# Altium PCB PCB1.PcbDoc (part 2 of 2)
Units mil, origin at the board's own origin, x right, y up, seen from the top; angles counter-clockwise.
Board outline 3937.01 x 3937.01 mil, 2 copper layers (Top Layer, Bottom Layer), stack 65.792 mil thick; 127 components, 100 nets, 530 pads, 138 vias.
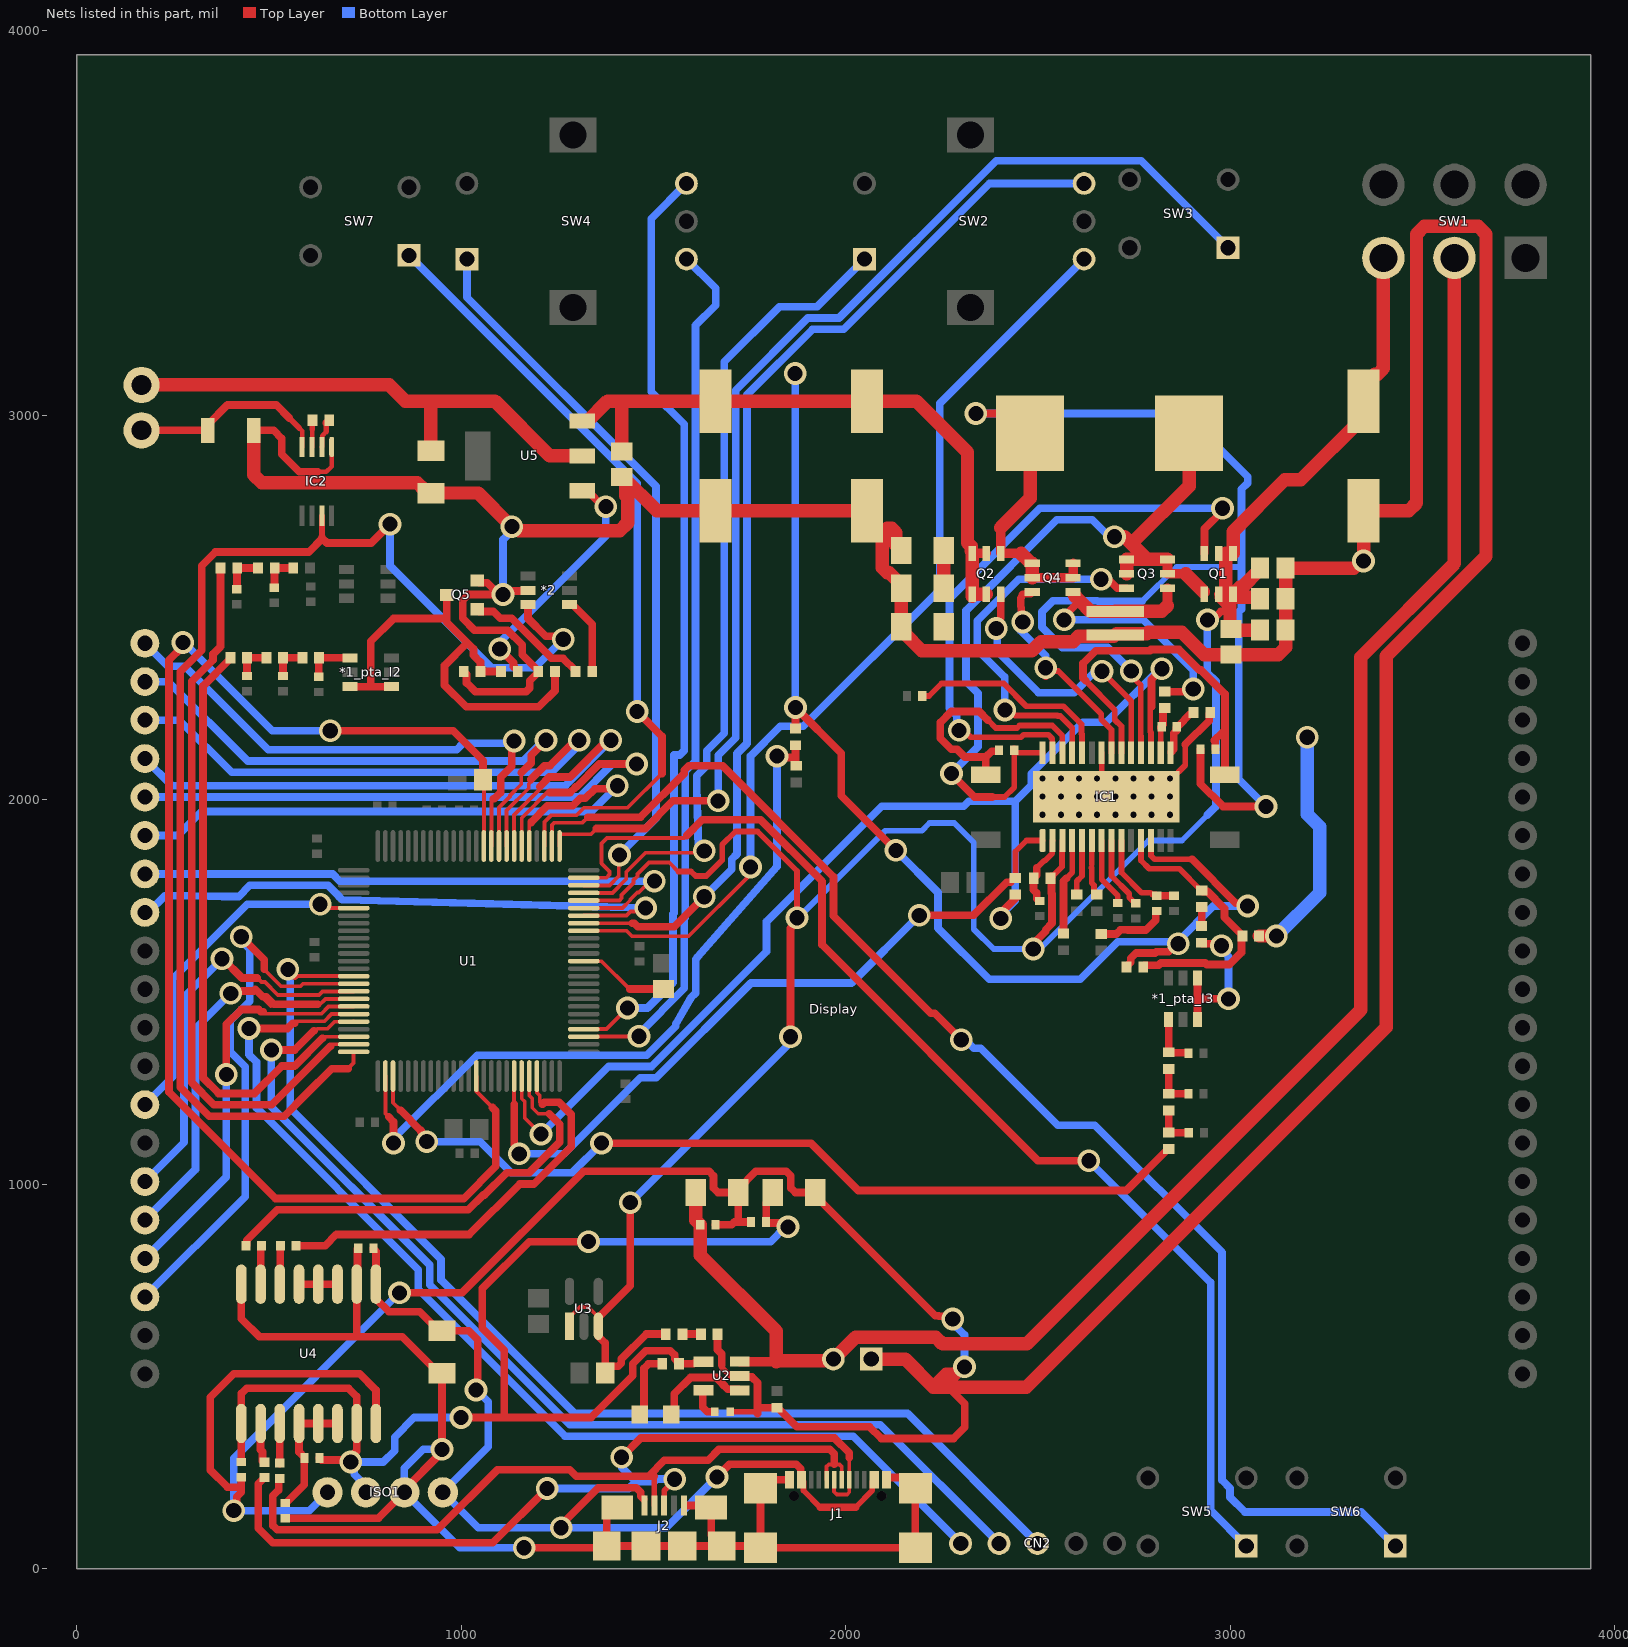
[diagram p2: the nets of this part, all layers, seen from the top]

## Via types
v1: diameter 59.06, hole 39.37, Top Layer to Bottom Layer, 110 vias
v2: diameter 19.68, hole 15.75, Top Layer to Bottom Layer, 12 vias
v3: diameter 19.68, hole 15.75, Top Layer to Bottom Layer, tented top, 6 vias
v4: diameter 19.68, hole 15.75, Top Layer to Bottom Layer, tented both sides, 6 vias
v5: diameter 137.8, hole 118.11, Top Layer to Bottom Layer, 4 vias

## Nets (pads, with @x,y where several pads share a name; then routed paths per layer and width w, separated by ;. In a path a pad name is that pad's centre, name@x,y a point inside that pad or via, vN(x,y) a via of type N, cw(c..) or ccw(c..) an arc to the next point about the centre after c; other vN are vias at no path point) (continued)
Net*1_pta_I2_1: *1_pta_I2.1 C41_pta_I2.2 R22_pta_I2.2 | length 130.8
  Top Layer w20: C41_pta_I2.2@629.11,2319.55 629.6,2320.04 629.6,2368.7 R22_pta_I2.2@630.1,2369.19 630.37,2368.92 710.36,2368.92 *1_pta_I2.1@710.63,2368.64
Net*1_pta_I2_3: *1_pta_I2.3 *1_pta_I2.4 Q5.3 R31.1 R32.2 R33.2 | length 1250.4
  Top Layer w20: *1_pta_I2.3@710.63,2293.84 764.76,2293.84 ; *1_pta_I2.4@818.9,2293.84 764.76,2293.84 ; Q5.3@962.4,2532.48 962.4,2471.06 ; R31.1@1103.35,2333.21 R32.2@1049.76,2333.21 1049.76,2357.75 1031.47,2376.04 1031.47,2392.3 1015.8,2407.97 ; R33.2@1243.55,2333.21 1243.55,2283.46 1201.23,2241.14 1012.81,2241.14 956.38,2297.58 956.38,2348.55 1015.8,2407.97 ; 764.76,2293.84 764.76,2411.99 823.83,2471.06 962.4,2471.06 ; 962.4,2471.06 962.4,2461.37 1015.8,2407.97
Net*1_pta_I3_1: *1_pta_I3.1 C41_pta_I3.2 R22_pta_I3.2 | length 137
  Top Layer w20: *1_pta_I3.1@2839.57,1427.81 R22_pta_I3.2@2839.57,1342.97 2840.78,1341.76 2889.54,1341.76 C41_pta_I3.2@2890.75,1340.55
Net*1_pta_I3_3: *1_pta_I3.3 *1_pta_I3.4 R16.2 | length 390.3
  Top Layer w20: *1_pta_I3.3@2914.37,1427.81 2914.37,1481.95 ; *1_pta_I3.4@2914.37,1536.08 2914.37,1481.95 ; R16.2@2924.86,1627.96 2927.65,1625.16 2971.84,1625.16 v1(2977,1620) ; v1(2995.29,1481.95) 2914.37,1481.95
  Bottom Layer w20: v1(2977,1620) 2977,1609.43 2995.29,1591.14 v1(2995.29,1481.95)
Net*2_3: *2.3 IC2.7 U1.25 | length 3400.7
  Top Layer w10: 705.71,1300.48 720.03,1314.81 U1.25@720.03,1343.96
  Top Layer w15: 637.48,2681.33 IC2.7@637.48,2737.89
  Top Layer w20: 637.48,2681.33 637.07,2680.92 638.91,2679.09 ; 705.71,1300.48 663.02,1300.48 595.74,1233.21 539.51,1176.97 344.25,1176.97 269.2,1252.03 269.2,2332.66 324.99,2388.46 324.99,2608.47 360.3,2643.78 603.6,2643.78 638.91,2679.09 ; v1(814.52,2716.33) 765.52,2667.32 650.67,2667.32 638.91,2679.09 ; *2.3@1173.38,2506.89 1173.38,2471.09 1220,2424.47 1257.53,2424.47 v1(1265,2417)
  Bottom Layer w20: v1(814.52,2716.33) 814.52,2607.84 1079.58,2342.78 1190.78,2342.78 v1(1265,2417)
Net*2_4: *2.4 R34.2 | length 202.7
  Top Layer w20: *2.4@1281.64,2506.89 1289.52,2506.89 1340.45,2455.96 R34.2@1340.45,2333.21
NetC11_2: C11.2 U1.63 | length 237.4
  Top Layer w10: U1.63@1318.46,1580.18 1318.8,1579.83 1364.75,1579.83 1437.23,1507.34 1438.04,1507.34
  Top Layer w20: 1438.04,1507.34 C11.2@1525.69,1507.34
NetC12_2: C12.2 U1.39 U1.86 | length 3570.1
  Top Layer w10: U1.39@1038.93,1280.96 1039.28,1280.62 1039.28,1240.96 1080.89,1199.35 ; U1.86@1058.62,1879.39 C12.2@1058.62,2049.41
  Top Layer w20: v1(275.96,2408.76) 275.96,2398.2 239.7,2361.93 239.7,1239.81 516.95,962.56 1006.09,962.56 1089.93,1046.4 1089.93,1190.31 1080.89,1199.35 ; v1(659.01,2179.01) 978.75,2179.01 1056.54,2101.22 C12.2@1056.54,2051.48 C12.2@1058.62,2049.41
  Bottom Layer w20: v1(275.96,2408.76) 278.69,2408.76 508.45,2179.01 v1(659.01,2179.01)
NetC13_2: C13.2 C14.2 C45.2 C46.2 ISO1.3 R1.2 U2.4 U4.9 U4.15 | length 3318
  Top Layer w20: C45.2@428.03,277.36 U4.9@428.03,377.55 428.03,455.41 441.81,469.19 706.42,469.19 728.03,447.58 U4.15@728.03,377.55 728.03,306.12 712.54,290.64 v1(712.54,277.36) 707.31,282.59 636.41,282.59 C46.2@631.18,287.82 ; v1(999.32,393.33) 1111.77,393.33 ; v1(1330.95,850.45) 1176.74,850.45 1054.86,728.57 1054.86,625.02 1111.77,568.11 1111.77,393.33 ; U2.4@1629.92,538.63 1626.14,534.85 1606.77,534.85 1604.55,532.63 R1.2@1565.95,532.63 1563.15,535.42 1563.15,537.39 1554.93,545.61 1554.93,555.47 1543.51,566.89 1479.59,566.89 1445.83,533.13 1445.83,501.56 1337.6,393.33 1111.77,393.33 ; C13.2@1810.43,978.41 1810.43,969.55 1792.72,951.83 1792.72,899.67 1793.35,899.04 1829.23,899.04 1839.23,889.04 v1(1849.8,889.04)
  Bottom Layer w20: ISO1.3@751.91,198.62 751.91,215.55 721.93,245.53 721.93,267.98 v1(712.54,277.36) 797.25,277.36 826.57,306.68 826.57,342.02 877.88,393.33 v1(999.32,393.33) ; v1(1330.95,850.45) 1804.21,850.45 1842.8,889.04 v1(1849.8,889.04)
NetC15_2: C15.2 C16.2 P1.2 SW1.2 U2.3 | length 4590.2
  Top Layer w25: U2.3@1724.41,538.63 1818.82,538.63
  Top Layer w35: C15.2@1609.64,978.41 1609.64,906.56 C16.2@1621.46,894.75 1621.46,815.37 1818.82,618.01 1818.82,538.63 ; 1818.82,540.61 1962.92,540.61 P1.2@1967.52,545.21 1968.7,545.21 2025.23,601.74 2234.03,601.74 2251.39,584.38 2470.55,584.38 3339.12,1452.96 3339.12,2370.53 3582.68,2614.09 SW1.2@3582.68,3408.86
NetC17_1: C17.1 C23.2 C24.2 C25.2 C26.2 C37.2 IC1.3 Q1.2 R3.2 R6.2 SW1.3 U1.71 U3.1 U3.3 | length 6521.1
  Top Layer w10: U3.1@1281.5,630.49 1281.5,653.98 1292.35,664.83 1292.35,664.98 1307.9,680.53 1329.9,680.53 1356.3,654.13 U3.3@1356.3,652.98 ; U1.71@1318.46,1737.66 1411.12,1737.66 1417.03,1743.56 1417.03,1751.64 1448.15,1782.77 1448.15,1790.85 1457.97,1800.67 1457.97,1806.24 1488.29,1836.55 1540.83,1836.55 1563.98,1813.4
  Top Layer w15: 1563.98,1813.4 1597.43,1813.4 1609.64,1801.18 1637.17,1801.18 1678.3,1842.32 1678.3,1882.71 1712.84,1917.24 1770,1917.24 1872.98,1814.27 v1(1872.98,1692.92) ; R6.2@2536.66,1800.05 2562.05,1825.43 2562.05,1856.91 2562.28,1857.13 2562.28,1866.19 2562.62,1866.53 2562.62,1893.33 IC1.3@2562.99,1893.7
  Top Layer w20: C37.2@1374.22,508.7 C37.2@1374.22,512.64 ; v1(1439.47,951.83) 1439.47,736.15 1356.3,652.98 U3.3@1356.3,630.49 1356.3,604.58 1374.22,586.67 C37.2@1374.22,512.64 ; R3.2@1531.5,610.09 1481.07,610.09 1416.33,545.35 1416.33,534.75 1407.84,526.26 1387.84,526.26 C37.2@1374.22,512.64 ; v1(1856.25,1383.33) 1856.25,1665.62 1872.98,1682.35 v1(1872.98,1692.92) ; v1(2487.45,1611.28) 2487.45,1625.45 2519.6,1657.6 2519.6,1661.96 2536.04,1678.39 2536.04,1755.18 2534.69,1756.52 2534.69,1792.49 R6.2@2531.9,1795.28 2531.9,1797.25 2534.69,1800.05 R6.2@2536.66,1800.05 ; v1(2940.26,2467.38) 2953.53,2467.38 2975.86,2489.71 2986.72,2489.71 2999.01,2477.42
  Top Layer w25: Q1.2@2969.48,2533.95 2988.19,2533.95
  Top Layer w35: Q1.2@2976.67,2526.76 2999.01,2504.42 2999.01,2477.42 2999.01,2455.08 3001.98,2452.11 C23.2@3001.98,2443.96 ; C23.2@3001.98,2440.95 C24.2@3076.77,2440.95 ; Q1.2@3006.89,2526.34 3072.83,2526.34 C25.2@3076.77,2522.4 ; C26.2@3076.77,2602.2 3076.77,2598.27 3030.29,2551.79 3024.73,2551.79 Q1.2@3006.89,2533.95 2988.19,2533.95 2988.19,2640.25 Q1.2@3006.89,2640.25 3006.89,2696.89 3141.56,2831.56 3182.9,2831.56 3346.42,2995.08 C17.1@3346.42,3036.42 3346.42,3077.76 3375.26,3106.6 3382.99,3106.6 3397.64,3121.24 SW1.3@3397.64,3408.86
  Bottom Layer w15: v1@1894.63,1711.14 2102.78,1919.29 2197.71,1919.29 2217.88,1939.46 2281.77,1939.46 2332.84,1888.4 2332.84,1663.09 2384.65,1611.28 2483.84,1611.28 2504.34,1611.28 2786.76,1893.7 2874.02,1893.7 2940.26,1959.94
  Bottom Layer w20: v1(1439.47,951.83) 1856.25,1368.61 v1(1856.25,1383.33) ; 2940.26,1959.94 2962.54,1982.23 2962.54,2308 2940.26,2330.29 v1(2940.26,2467.38)
NetC18_1: C18.1 C19.1 C20.2 C21.2 C22.2 C47.2 IC1.12 Q2.2 R13.2 R29.2 U5.3 | length 4856.5
  Top Layer w15: IC1.12@2793.31,1893.7 2793.68,1893.33 2793.68,1853.94 2802.95,1844.67 2900.41,1844.67
  Top Layer w20: R29.2@1869.05,2184.77 v1(1869.05,2239.54) 1988.15,2120.44 1988.15,2010 v1(2130.03,1868.12) ; R13.2@2730.03,1564.62 2732.83,1567.42 2732.83,1569.39 2741.05,1577.6 2741.05,1587.46 2754.85,1601.27 2803.96,1601.27 2807.46,1604.77 2838.88,1604.77 2859.11,1625 v1(2864.4,1625) ; 2900.41,1844.67 3014.32,1730.76 3037.43,1730.76 v1(3044.9,1723.29)
  Top Layer w25: Q2.2@2328.21,2640.25 Q2.2@2365.61,2640.25
  Top Layer w35: U5.3@1314.42,2984.25 1328.2,2984.25 1380.36,3036.42 1421.26,3036.42 ; C47.2@1417.32,2905.51 1417.32,3032.48 1421.26,3036.42 ; C21.2@2254.34,2549.7 C22.2@2254.34,2647.64 ; Q2.2@2325.55,2647.43 2325.55,2658.51 2316.35,2667.72 2316.35,2903.6 2183.52,3036.42 C19.1@2055.08,3036.42 C18.1@1661.38,3036.42 1421.26,3036.42 ; Q2.2@2328.21,2529.42 Q2.2@2328.21,2533.95 ; Q2.2@2328.21,2640.25 Q2.2@2328.21,2533.95 ; Q2.2@2365.61,2533.95 Q2.2@2328.21,2533.95
  Bottom Layer w20: v1(1868.07,3108.27) 1868.56,3107.78 1868.56,2240.03 v1(1869.05,2239.54) ; v1(2130.03,1868.12) 2239.76,1758.39 2239.76,1665.9 2372.92,1532.75 2609.53,1532.75 2707.55,1630.77 2862.88,1630.77 2955.4,1723.29 v1(3044.9,1723.29)
NetC27_1: C27.1 IC1.2 R6.1 | length 188.3
  Top Layer w15: 2496.38,1821.97 2515.29,1840.87 2518.12,1840.87 2537.03,1859.78 2537.03,1893.33 IC1.2@2537.4,1893.7
  Top Layer w20: R6.1@2488.59,1795.28 R6.1@2487.85,1794.54 ; 2496.38,1821.97 2496.38,1803.08 R6.1@2487.85,1794.54 ; C27.1@2503.94,1736.47 2501.97,1736.47 2496.34,1742.1 2496.34,1757.03 2487.85,1765.52 R6.1@2487.85,1794.54
NetC28_1: C28.1 IC1.28 L1.1 Q1.1 Q3.2 | length 2084
  Top Layer w15: 2380.7,2006.66 2412.58,2006.66 2437.79,2031.87 C28.1@2437.79,2126.7 ; C28.1@2437.79,2128.67 C28.1@2437.79,2126.7 ; IC1.28@2511.81,2122.05 2442.44,2122.05 C28.1@2437.79,2126.7
  Top Layer w20: v1(2274.56,2068.01) 2274.56,2066.88 2334.78,2006.66 2380.7,2006.66 ; C28.1@2437.16,2131.26 2437.16,2129.3 C28.1@2437.79,2128.67
  Top Layer w25: Q3.2@2836.5,2624.5 Q3.2@2836.5,2587.1 2883.46,2587.1
  Top Layer w35: v1(2698.86,2683.75) 2724.64,2683.2 2742.68,2665.17 2783.35,2624.5 ; Q3.2@2730.2,2587.1 Q3.2@2730.2,2624.5 2783.35,2624.5 ; 2750.31,2672.8 2892.47,2814.96 L1.1@2892.47,2952.76 ; Q3.2@2836.5,2624.5 2783.35,2624.5 ; 2883.46,2587.1 Q1.1@2929.42,2541.13
  Bottom Layer w20: v1(2274.56,2068.01) 2343.77,2137.23 2343.77,2276.23 2312.47,2307.53 2312.47,2491.61 2548.99,2728.13 2640.74,2728.13 2685.11,2683.75 v1(2698.86,2683.75)
NetC28_2: C28.2 D2.1 IC1.26 | length 673.2
  Top Layer w15: 2369.37,2206.83 2389.73,2186.47 2445.29,2186.47 2451.89,2193.08 2536.88,2193.08 2562.99,2166.96 IC1.26@2562.99,2122.05
  Top Layer w20: D2.1@2364.09,2064.97 2364.09,2110.87 ; 2369.37,2206.83 2347.16,2229.05 2274.44,2229.05 2245.72,2200.33 2245.72,2159.71 2274.44,2130.99 2288.99,2130.99 2309.11,2110.87 2364.09,2110.87 ; C28.2@2398.42,2128.67 2398.42,2126.7 2397.79,2126.07 2379.29,2126.07 2364.09,2110.87
NetC29_1: C29.1 IC1.16 R9.1 | length 122.2
  Top Layer w15: IC1.16@2818.9,2122.05 C29.1@2818.9,2187.37
  Top Layer w20: C29.1@2818.9,2187.37 C29.1@2821.39,2189.86 ; C29.1@2822.02,2188.63 2822.02,2192.46 2824.8,2195.24 2824.8,2235.24 2827.59,2238.03 R9.1@2829.26,2238.03
NetC29_2: C29.2 IC1.15 R12.1 | length 137.4
  Top Layer w15: IC1.15@2844.49,2122.05 IC1.15@2847.02,2124.58
  Top Layer w20: IC1.15@2847.02,2124.58 2853.03,2130.59 2853.03,2172.35 2860.13,2179.44 2860.13,2187.26 2860.76,2187.89 C29.2@2860.76,2189.86 ; C29.2@2861.03,2187.79 2861.03,2192.11 2861.39,2192.46 2865.71,2192.46 2894.87,2221.62 2901.39,2221.62 2904.19,2224.42 R12.1@2904.19,2226.38
NetC30_2: C30.2 IC1.8 | length 190.5
  Top Layer w15: IC1.8@2690.95,1893.7 2690.95,1801.27 2736.82,1755.4 2736.82,1745.19 2751.69,1730.32 C30.2@2753.66,1730.32
NetC32_1: C32.1 IC1.18 L1.2 Q2.1 Q4.2 | length 3847.7
  Top Layer w15: v1(2742.13,2334.57) 2742.13,2322.65 2766.63,2298.15 2766.63,2166.81 2767.72,2165.72 IC1.18@2767.72,2122.05
  Top Layer w20: v1(2338.05,3003.94) 2427.9,3003.94 L1.2@2479.09,2952.76 ; C32.1@2922.1,2131.26 2922.1,2041.13 2981,1982.23 v1(3092.52,1982.23)
  Top Layer w25: 2403.01,2707.55 Q2.1@2403.01,2640.25 2455.67,2640.25 ; Q4.2@2484.83,2577.25 Q4.2@2591.13,2577.25 Q4.2@2591.13,2614.65
  Top Layer w35: 2403.01,2707.55 2479.09,2783.63 L1.2@2479.09,2952.76 ; 2455.67,2640.25 2477.64,2618.27 2477.64,2617.31 2480.3,2614.65 Q4.2@2484.83,2614.65 Q4.2@2484.83,2577.25
  Bottom Layer w15: 2771.07,2515.81 2860.07,2604.81 3028.7,2604.81
  Bottom Layer w20: v1(2338.05,3003.94) 2880.77,3003.94 3044.87,2839.85 3044.87,2823.28 3028.7,2807.11 3028.7,2604.81 3028.7,2494.85 3021.66,2487.81 3021.66,2053.09 v1(3092.52,1982.23) ; v1(2742.13,2334.57) 2681.15,2395.54 2562.68,2395.54 2510.03,2448.2 2510.03,2488.81 2538.75,2517.53 2654.05,2517.53 2655.77,2515.81 2771.07,2515.81
NetC32_2: C32.2 D3.1 IC1.20 | length 969.4
  Top Layer w15: 2623.82,2308.86 2699.31,2233.38 2699.31,2207.79 2716.54,2190.56 IC1.20@2716.54,2122.05
  Top Layer w20: 2623.82,2308.86 2616.93,2315.75 2616.93,2354.23 2650.19,2387.49 2790.82,2387.49 2793.51,2390.18 2866.34,2390.18 2919.66,2336.86 2923.59,2336.86 2985.88,2274.57 D3.1@2985.88,2064.97 ; C32.2@2961.47,2131.26 2960.84,2131.89 2960.84,2151.13 2958.11,2153.86 2979.79,2175.54
NetC33_1: C33.1 R18.2 | length 183.7
  Top Layer w20: R18.2@2664.01,1650.6 2703.6,1650.6 2714.45,1661.45 2732.35,1661.45 2732.98,1660.82 2780.07,1660.82 2805.86,1686.6 2805.86,1707.72 2806.17,1708.04 2806.17,1710 2806.8,1710.63 C33.1@2808.77,1710.63
NetC33_2: C33.2 C35.2 IC1.9 | length 245.3
  Top Layer w15: IC1.9@2716.54,1893.7 2716.54,1810.33 2768.92,1757.95 2792.48,1757.95 2797.29,1753.13 2805.64,1753.13 C33.2@2808.77,1750
  Top Layer w20: C33.2@2808.77,1750 C35.2@2853.52,1750.01
NetC34_2: C34.2 IC1.7 | length 179.7
  Top Layer w15: IC1.7@2665.35,1893.7 2665.35,1792.22 2707.22,1750.35 C34.2@2707.22,1731.3
NetC39_pta_I1_2: C39_pta_I1.2 R20_pta_I1.2 R21_pta_I1.1 | length 109.7
  Top Layer w20: C39_pta_I1.2@416.34,2547.24 416.83,2547.74 416.83,2601.87 R20_pta_I1.2@417.32,2602.36 R21_pta_I1.1@471.46,2602.36
NetC39_pta_I2_2: C39_pta_I2.2 R20_pta_I2.2 R21_pta_I2.1 | length 97.7
  Top Layer w20: C39_pta_I2.2@442.87,2321.4 R20_pta_I2.2@442.87,2368.64 443.14,2368.92 492.84,2368.92 R21_pta_I2.1@493.11,2369.19
NetC39_pta_I3_2: C39_pta_I3.2 R20_pta_I3.2 R21_pta_I3.1 | length 109.7
  Top Layer w20: R20_pta_I3.2@2839.57,1134.51 R21_pta_I3.1@2839.57,1191.59 ; R20_pta_I3.2@2839.57,1134.51 2840.06,1134.01 2891.3,1134.01 C39_pta_I3.2@2891.79,1133.52
NetC40_pta_I1_2: C40_pta_I1.2 R21_pta_I1.2 R22_pta_I1.1 | length 100
  Top Layer w20: C40_pta_I1.2@513.78,2551.18 514.28,2551.67 514.28,2601.87 R21_pta_I1.2@514.77,2602.36 R22_pta_I1.1@563.16,2602.36
NetC40_pta_I2_2: C40_pta_I2.2 R21_pta_I2.2 R22_pta_I2.1 | length 98.2
  Top Layer w20: C40_pta_I2.2@536.42,2321.4 R21_pta_I2.2@536.42,2369.19 R22_pta_I2.1@586.79,2369.19
NetC40_pta_I3_2: C40_pta_I3.2 R21_pta_I3.2 R22_pta_I3.1 | length 115.9
  Top Layer w20: R22_pta_I3.1@2839.57,1299.66 R21_pta_I3.2@2839.57,1234.9 C40_pta_I3.2@2890.75,1234.9
NetC42_1: C42.1 C43.1 C44.2 ISO1.2 J1.1 J1.2 J1.3 J1.4 J1.A1-B12 J1.B1-A12 J2.5 J2.6 J2.7 J2.8 J2.9 J2.10 J2.11 U4.2 U4.8 | length 3933.5
  Top Layer w20: U4.8@428.03,739.75 428.03,650.1 475.17,602.95 728.03,602.95 ; C44.2@541.81,131.21 784.5,131.21 ISO1.2@851.91,198.62 ; C43.1@732.11,833.21 730.07,831.17 730.07,741.79 U4.2@728.03,739.75 728.03,602.95 ; ISO1.2@848.49,202.04 949.88,303.43 v1(949.88,310.26) C42.1@949.88,508.7 941.02,508.7 846.77,602.95 728.03,602.95 ; v1(1163.39,54.28) 1373.18,54.28 J2.8@1377.95,59.06 ; J2.6@1404.45,159.45 1377.95,132.95 J2.8@1377.95,59.06 ; 1586.61,164.37 1644.69,164.37 J2.7@1649.61,159.45 1649.61,86.61 J2.9@1677.17,59.06 ; J1.A1-B12@1853.35,231.65 1800.79,231.65 J1.1@1778.15,209.01 J1.3@1778.15,54.28 ; J1.B1-A12@2105.31,231.65 2111.02,237.36 2152.16,237.36 J1.2@2180.51,209.01 J1.4@2180.51,54.28 J1.3@1778.15,54.28 ; J2.8@1377.95,59.06 J2.11@1574.8,59.06 J2.9@1677.17,59.06 ; J2.9@1677.17,59.06 1773.38,59.06 J1.3@1778.15,54.28
  Bottom Layer w20: v1(949.88,310.26) 900.81,310.26 851.91,261.36 ISO1.2@851.91,198.62 996.25,54.28 v1(1163.39,54.28)
NetC42_2: C42.2 C43.2 ISO1.1 J1.A4-B9 J1.B4-A9 J2.1 U4.1 | length 2522.9
  Top Layer w15: J1.A4-B9@1884.84,231.65 1890.03,226.46 1890.03,203 1933.58,159.45 ; 2025.08,159.45 2068.63,203 2068.63,226.46 J1.B4-A9@2073.82,231.65
  Top Layer w20: C43.2@771.48,833.21 771.48,831.24 778.03,824.69 778.03,702.35 812.17,668.21 891.75,668.21 C42.2@941.02,618.93 ; C42.2@949.88,618.93 1019.23,618.93 1042.87,595.29 1042.87,469.19 v1(1038.46,464.78) ; v1(1259.64,106.45) 1259.64,113.99 1356.1,210.45 1454.93,210.45 1466.35,199.02 1466.35,188.85 J2.1@1474.25,180.95 ; v1(1664.75,238.46) 1697.55,271.26 1871.31,271.26 1883.03,259.54 1883.03,233.46 J1.A4-B9@1884.84,231.65 ; 1933.58,159.45 2025.08,159.45
  Bottom Layer w20: v1(1038.46,464.78) 1039.42,464.78 1070.43,433.78 1070.43,317.14 ISO1.1@951.91,198.62 1044.08,106.45 v1(1259.64,106.45) 1532.74,106.45 v1(1664.75,238.46)
NetC44_1: C44.1 C46.1 U4.12 U4.13 U4.14 | length 334.5
  Top Layer w20: C44.1@541.81,170.58 543.78,170.58 591.81,218.61 591.81,289.79 578.03,303.57 U4.12@578.03,377.55 U4.13@628.03,377.55 U4.14@678.03,377.55
NetC48_2: C48.2 CN1.1 U5.2 | length 1351.3
  Top Layer w35: CN1.1@168.5,3078.29 812.55,3078.29 854.42,3036.42 920.94,3036.42 ; C48.2@920.94,2907.48 920.94,3036.42 ; U5.2@1314.42,2893.7 1230.32,2893.7 1087.6,3036.42 920.94,3036.42
NetCN1_2: CN1.2 IC2.4 R27.1 | length 523.6
  Top Layer w12: 578.57,2966.33 586.3,2958.6 IC2.4@586.3,2917.03
  Top Layer w15: 552.39,2992.52 578.57,2966.33
  Top Layer w20: CN1.2@168.5,2960.18 R27.1@340.42,2960.18 340.42,2974.94 391.9,3026.43 518.47,3026.43 552.39,2992.52
NetCN2_1: CN2.1 U1.20 | length 2837.4
  Top Layer w10: 561.72,1418.69 566.72,1423.69 644.14,1423.69 662.83,1442.38 U1.20@720.03,1442.38
  Top Layer w20: v1(448,1405) 548.03,1405 561.72,1418.69 566.72,1418.69
  Bottom Layer w20: v1(448,1405) 448,1337.05 467.53,1317.53 467.53,1198.23 888.14,777.61 888.14,726.45 1269.9,344.69 2019.28,344.69 CN2.1@2298.43,65.55
NetCN2_2: CN2.2 U1.21 | length 2783.9
  Top Layer w10: 618.53,1397.41 625.32,1404.19 652.22,1404.19 670.38,1422.35 719.69,1422.35 U1.21@720.03,1422.7
  Top Layer w20: v1(506,1349) 566.55,1349 616.74,1399.19
  Bottom Layer w20: v1(506,1349) 506,1201.47 917.64,789.83 917.64,738.67 1282.12,374.19 2089.78,374.19 CN2.2@2398.43,65.55
NetCN2_3: CN2.3 U1.15 | length 2986.1
  Top Layer w10: v1@566.55,1540.99 719.85,1540.99 U1.15@720.03,1540.81
  Top Layer w20: v1(549.02,1558.52) v1@566.55,1540.99
  Bottom Layer w20: v1(549.02,1558.52) 555.03,1552.52 555.03,1196.95 947.14,804.84 947.14,750.89 1294.34,403.69 2160.28,403.69 CN2.3@2498.43,65.55
NetDisplay_23: Display.23 U1.16 | length 1454.5
  Top Layer w10: 487.77,1558.52 487.77,1557.51 530.78,1514.5 581.54,1514.5 588.16,1521.12 U1.16@720.03,1521.12
  Top Layer w20: v1(427.69,1643.41) 487.77,1583.33 487.77,1558.52
  Bottom Layer w20: Display.23@177.17,706.69 438.03,967.56 438.03,1305.31 398.97,1344.36 398.97,1425.31 427.69,1454.03 449.47,1475.8 449.47,1611.06 427.69,1632.84 v1(427.69,1643.41)
NetDisplay_24: Display.24 U1.19 | length 1060.8
  Top Layer w10: 479.06,1448.19 484.06,1443.19 636.07,1443.19 654.94,1462.07 U1.19@720.03,1462.07
  Top Layer w20: v1(389,1285) 389,1415.34 427.69,1454.03 473.23,1454.03 479.06,1448.19 484.06,1448.19
  Bottom Layer w20: Display.24@177.17,806.69 389,1018.53 v1(389,1285)
NetDisplay_25: Display.25 U1.18 | length 1064.6
  Top Layer w10: 480.1,1487.19 486.51,1480.79 504.6,1462.69 ; 625.92,1462.69 627.99,1462.69 647.05,1481.75 U1.18@720.03,1481.75
  Top Layer w20: v1(400.44,1496.11) 406.81,1502.48 459.97,1502.48 464.18,1506.69 483.68,1487.19 492.91,1487.19 512.41,1467.69 625.92,1467.69
  Bottom Layer w20: Display.25@177.17,906.69 308.56,1038.09 308.56,1404.23 v1(400.44,1496.11)
NetDisplay_26: Display.26 U1.17 | length 1047.2
  Top Layer w10: 468.86,1536.67 480.23,1525.3 489.46,1525.3 522.56,1492.19 629.91,1492.19 639.15,1501.44 U1.17@720.03,1501.44
  Top Layer w20: v1(377.91,1586.08) 379.81,1586.08 429.69,1536.19 468.49,1536.19
  Bottom Layer w20: Display.26@177.17,1006.69 279.06,1108.59 279.06,1487.24 v1(377.91,1586.08)
NetDisplay_28: Display.28 U1.6 | length 912.6
  Top Layer w10: v1(633,1728) 646.27,1728 656.3,1717.97 U1.6@720.03,1717.97
  Bottom Layer w20: Display.28@177.17,1206.69 249.56,1279.09 249.56,1534.61 442.95,1728 v1(633,1728)
NetDisplay_33: Display.33 U1.69 | length 1517.8
  Top Layer w10: U1.69@1318.46,1698.29 1429.71,1698.29 1440.19,1708.76 1470.05,1708.76 v1(1479.44,1718.15)
  Bottom Layer w20: Display.33@177.17,1706.69 186.19,1706.69 229.41,1749.91 301.88,1749.91 379.15,1747.83 421.06,1747.83 450.26,1777.03 653.31,1777.03 682.03,1748.31 682.03,1747.71 690.25,1739.49 1479.44,1718.31 v1(1479.44,1718.15)
NetDisplay_34: Display.34 U1.70 | length 1546.3
  Top Layer w10: U1.70@1318.46,1717.97 1419.02,1717.97 1439.19,1738.14 1439.19,1740.16 1448.3,1749.28 1457.42,1758.4 1461.59,1758.4 v1@1491.2,1788
  Top Layer w20: v1@1491.2,1788 v1(1502,1788)
  Bottom Layer w20: Display.34@177.17,1806.69 177.33,1806.53 665.53,1806.53 684.05,1788 v1(1502,1788)
NetDisplay_35: Display.35 U1.80 | length 1611.5
  Top Layer w10: U1.80@1176.73,1879.39 1176.72,1940.41 1179.13,1942.82
  Top Layer w20: 1181.54,1940.41 1181.54,1941.61 1223.97,1984.04 1290.19,1984.04 1309.33,2003.18 1322.42,2003.18 1347.86,2028.62 1398.43,2028.62 v1(1405.9,2036.1)
  Bottom Layer w20: Display.35@177.17,1906.69 262.64,1906.69 325.16,1969.22 1339.02,1969.22 v1(1405.9,2036.1)
NetDisplay_36: Display.36 U1.81 | length 1742.3
  Top Layer w10: U1.81@1157.04,1879.39 1157.04,1952.55 1226.76,2022.27
  Top Layer w20: 1230.3,2018.74 1283.16,2018.74 1297.11,2032.68 1298.49,2032.68 1358.34,2092.53 v1(1455.96,2092.53)
  Bottom Layer w20: Display.36@177.17,2006.69 1307.16,2006.69 1393,2092.53 v1(1455.96,2092.53)
NetDisplay_37: Display.37 U1.82 | length 1710.1
  Top Layer w10: U1.82@1137.36,1879.39 1137.36,1960.44 1210.95,2034.04
  Top Layer w20: 1203.65,2033.81 1228.55,2058.71 1282.8,2058.71 1378.35,2154.26 v1(1388.92,2154.26)
  Bottom Layer w20: Display.37@177.17,2106.69 247.67,2036.19 1270.85,2036.19 v1(1388.92,2154.26)
NetDisplay_38: Display.38 U1.83 | length 1592.5
  Top Layer w10: U1.83@1117.67,1879.39 1117.67,1971.63 1175.45,2029.4 1175.45,2040.26 1183.99,2048.79
  Top Layer w20: 1180.45,2052.33 1216.33,2088.21 1230.47,2088.21 1296.77,2154.51 v1(1306.38,2154.51)
  Bottom Layer w20: Display.38@177.17,2206.69 266.93,2206.69 402.64,2070.98 1234.61,2070.98 1306.99,2143.36 1306.99,2153.9 v1(1306.38,2154.51)
NetDisplay_39: Display.39 U1.84 | length 1476.3
  Top Layer w10: U1.84@1097.99,1879.39 1097.99,1979.52 1126.97,2008.5 1126.97,2011.07 1155.95,2040.05 1155.95,2069.55
  Top Layer w20: 1155.95,2069.55 1181.54,2095.14 1181.54,2115.53 v1(1220.27,2154.26)
  Bottom Layer w20: Display.39@177.17,2306.69 238.06,2306.69 444.27,2100.48 1161.22,2100.48 1214.99,2154.26 v1(1220.27,2154.26)
NetDisplay_40: Display.40 U1.85 | length 1414.8
  Top Layer w10: U1.85@1078.3,1879.39 1078.3,2001.55 1102.47,2025.72
  Top Layer w20: 1083.12,2001.86 1085.68,2001.86 1102.47,2018.65 1102.47,2025.72 1102.47,2057.78 1131.45,2086.77 1131.45,2146.38 v1(1137.36,2152.29)
  Bottom Layer w20: Display.40@177.17,2406.69 236.98,2346.87 281.17,2346.87 498.06,2129.98 988.01,2129.98 1004.41,2146.38 1131.45,2146.38 v1(1137.36,2152.29)
NetIC1_1: IC1.1 R7.2 U1.44 | length 1949.6
  Top Layer w10: 1137.36,1207.36 U1.44@1137.36,1283.92
  Top Layer w15: R7.2@2440.95,1796.27 2440.95,1865.01 2469.64,1893.7 IC1.1@2511.81,1893.7
  Top Layer w20: 1137.36,1207.36 1137.36,1102.65 1150.65,1089.36 v1(1150.65,1078.79) ; v1(2190.74,1699.07) 2331.92,1699.07 2418.11,1785.25 2427.96,1785.25 2436.18,1793.47 2438.15,1793.47 R7.2@2440.95,1796.27
  Bottom Layer w20: v1(1150.65,1078.79) 1267.58,1078.79 1465.39,1276.6 1506.98,1276.6 1753.48,1523.09 2014.76,1523.09 v1(2190.74,1699.07)
NetIC1_4: IC1.4 R8.2 | length 251.6
  Top Layer w15: 2573.72,1795.28 2588.58,1810.14 IC1.4@2588.58,1893.7
  Top Layer w20: R8.2@2565.93,1651.44 2565.93,1787.49 2573.72,1795.28
NetIC1_5: IC1.5 R14.2 | length 146.4
  Top Layer w15: R14.2@2600.83,1753 2600.83,1758.14 2600.72,1758.25 2600.72,1787.63 2614.17,1801.09 IC1.5@2614.17,1893.7
  Top Layer w20: R14.2@2600.8,1752.96 R14.2@2600.87,1753.03
NetIC1_6: IC1.6 R10.2 | length 139
  Top Layer w15: 2638.67,1822.64 2639.76,1821.55 2639.76,1783.16 2645.7,1777.22 2645.7,1758.3 2650.99,1753.01 R10.2@2652.96,1753.01 ; 2639.76,1831.45 IC1.6@2639.76,1893.7
NetIC1_11: IC1.11 R13.1 R15.1 R17.2 | length 730.2
  Top Layer w15: IC1.11@2767.72,1893.7 2767.72,1841.7 2767.87,1841.55 2789.25,1820.17 2867.48,1820.17 2923.87,1763.78 R15.1@2925.84,1763.78
  Top Layer w20: R13.1@2773.34,1564.62 2773.34,1566.59 2776.14,1569.39 2813.8,1569.39 2819.68,1575.27 2934.26,1575.27 2938.55,1570.97 2997.31,1570.97 3028.7,1602.36 3028.7,1642.56 R17.2@3031.5,1645.35 ; R15.1@2925.84,1763.78 2928.64,1760.99 2940.47,1760.99 2984.58,1716.87 2984.58,1694.23 3028.7,1650.12 R17.2@3028.7,1645.35
NetIC1_17: IC1.17 R7.1 U1.45 | length 2984.8
  Top Layer w10: U1.45@1157.04,1280.96 1157.12,1280.89 1157.12,1222.25 1164.83,1214.54 1164.83,1172.17 v1(1207,1130)
  Top Layer w15: IC1.17@2793.31,2122.05 2793.31,2174.78 2791.9,2176.19 2791.9,2238.33 2794.72,2241.15
  Top Layer w20: v1(2403.01,1690.75) 2403.01,1705.18 2445.87,1748.04 R7.1@2440.95,1752.96 ; 2794.72,2241.15 2794.72,2311.48 2821.85,2338.62 v1(2821.85,2340.2)
  Bottom Layer w20: v1(1207,1130) 1383.1,1306.1 1494.76,1306.1 1793.84,1605.17 1793.84,1683.12 2093.49,1982.77 2306.68,1982.77 2319.53,1995.62 2440.95,1995.62 ; v1(2403.01,1690.75) 2403.01,1699.07 2440.95,1737 2440.95,1995.62 ; v1(2821.85,2340.2) 2817.09,2340.2 2677.68,2200.79 2615.99,2200.79 2482.47,2067.27 2482.47,2037.14 2440.95,1995.62
NetIC1_19: IC1.19 Q2.3 | length 705
  Top Layer w15: v1(2665.96,2333.92) 2665.96,2332.52 2742.13,2256.36 IC1.19@2742.13,2122.05
  Top Layer w20: 2403.01,2472.44 Q2.3@2403.01,2533.95
  Bottom Layer w20: v1(2391,2445) 2394.08,2441.92 2394.08,2385.47 2501.24,2278.31 2593.27,2278.31 2643.81,2328.85 2660.89,2328.85 v1(2665.96,2333.92)
NetIC1_21: IC1.21 Q4.3 | length 576.7
  Top Layer w15: v1(2519.69,2343) 2528.12,2334.57 2552.53,2334.57 2664.26,2222.84 2664.26,2208.19 2690.95,2181.51 IC1.21@2690.95,2122.05
  Top Layer w20: v1(2460.21,2462.05) 2454.56,2506.72 2454.56,2515.55 2455.01,2523.74 2459.99,2533.84 2466.28,2535.01 2479.99,2535.01 Q4.3@2484.83,2539.85 ; v1@2519.69,2321.24 v1(2519.69,2343)
  Bottom Layer w20: v1(2460.21,2462.05) 2454.4,2456.23 2454.4,2439.66 2519.69,2374.37 v1(2519.69,2343)
NetIC1_25: IC1.25 Q3.3 | length 963
  Top Layer w15: v1(2413.45,2233) 2425.17,2233 2439.67,2218.5 2549.87,2218.5 2551.07,2217.31 2557.35,2217.31 2588.58,2186.07 IC1.25@2588.58,2122.05
  Top Layer w20: v1(2663.86,2573) 2682.51,2573 2705.66,2549.85 2730.04,2549.85 Q3.3@2730.2,2549.7
  Bottom Layer w20: v1(2413.45,2233) 2413.45,2318.7 2341.97,2390.18 2341.97,2465.31 2449.66,2573 v1(2663.86,2573)
NetIC1_27: IC1.27 Q1.3 | length 1590.8
  Top Layer w15: v1(2294.74,2180.02) 2306.66,2180.02 2324.71,2161.97 2455.44,2161.97 2462.04,2168.58 2526.73,2168.58 2537.03,2158.28 2537.03,2122.42 IC1.27@2537.4,2122.05
  Top Layer w20: Q1.3@2932.08,2640.25 2932.82,2640.98 2932.82,2704.57 2979.67,2751.42 v1(2979.67,2757.63)
  Bottom Layer w20: v1(2294.74,2180.02) 2288.7,2186.06 2288.7,2218.16 2269.58,2237.28 2269.58,2522.83 2504.38,2757.63 v1(2979.67,2757.63)
NetIC2_2: IC2.2 R28.2 | length 77.9
  Top Layer w12: IC2.2@637.48,2917.03 637.97,2917.53 637.97,2946.33 648.89,2957.25
  Top Layer w15: 648.89,2957.25 R28.2@648.89,2979.22
  Top Layer w20: R28.2@648.89,2979.22 R28.2@656.69,2987.02
NetIC2_3: IC2.3 R28.1 | length 70.6
  Top Layer w12: IC2.3@611.89,2917.03 611.89,2962.65 612.64,2963.39
  Top Layer w15: 612.64,2963.39 R28.1@612.64,2986.27
  Top Layer w20: R28.1@612.64,2986.27 R28.1@613.38,2987.02
NetJ1_A6: J1.A6 J1.B6 J2.3 R23.1 | length 2271
  Top Layer w10: J1.A6@1969.49,231.65 1969.49,200.16 1976.64,193.01 2003,193.01 2008.86,198.87 J1.B6@2008.86,231.65 J1.B6@2008.86,231.65 2008.89,288.29
  Top Layer w15: J2.3@1527.56,164.37 1527.93,164.74 1527.93,203.63 1554.78,230.48 v1(1554.78,232.72)
  Top Layer w20: R23.1@487.77,236.69 486.79,236.69 484.98,234.88 484.98,233.9 471.98,220.9 471.98,105.66 510.12,67.52 1082.17,67.52 v1(1223.14,208.49) ; v1(1417.03,289.79) 1467,339.76 1970.32,339.76 2008.89,301.19 2008.89,288.29
  Bottom Layer w20: v1(1223.14,208.49) 1435.77,208.49 1453.74,226.46 ; v1(1417.03,289.79) 1417.03,263.17 1453.74,226.46 ; v1(1554.78,232.72) 1549.47,232.72 1548.91,233.29 1508.68,233.29 1501.85,226.46 1453.74,226.46
NetJ1_A7: J1.A7 J1.B7 J2.2 R25.1 | length 1931.3
  Top Layer w10: J1.B7@1949.8,231.65 1949.56,231.89 1949.56,265.4 1955.42,271.26 1969.82,271.26 1983.31,271.26 1989.17,265.4 J1.A7@1989.17,231.65
  Top Layer w15: J2.2@1501.97,164.37 1501.97,240.76
  Top Layer w20: R25.1@528.03,234.72 527.04,234.72 525.23,232.91 525.23,204.81 509.71,189.29 509.71,112.5 521.13,101.08 937.62,101.08 1094.06,257.52 1282.18,257.52 1298.93,240.76 1487.05,240.76 ; 1501.97,240.76 1487.05,240.76 ; 1969.82,271.26 1969.82,298.55 1958.1,310.26 1670.26,310.26 1641.75,281.75 1528.04,281.75 1487.05,240.76
NetLED1_1: LED1.1 U2.1 | length 259.5
  Top Layer w20: LED1.1@1546.36,400.83 1553.6,408.08 1553.6,454.45 1596.25,497.11 1663.59,497.11 1679.32,481.38 1679.32,480.36 1693.05,466.62 1721.61,466.62 U2.1@1724.41,463.83
NetLED1_2: LED1.2 R1.1 | length 177.1
  Top Layer w20: LED1.2@1463.68,400.83 1475.33,412.49 1475.33,520.91 1487.05,532.63 R1.1@1522.64,532.63
NetQ3_1: Q3.1 Q4.1 R9.2 R11.2 | length 895.4
  Top Layer w20: v1(2567.67,2467.38) 2567.67,2477.23 2607.98,2517.53 ; R9.2@2829.26,2281.34 2829.76,2280.85 2896.3,2280.85 v1(2903.29,2287.83)
  Top Layer w25: 2836.5,2504.35 Q3.1@2836.5,2549.7
  Top Layer w35: Q4.1@2593.31,2532.19 2607.98,2517.53 2636.28,2489.23 R11.2@2700.67,2489.23 2701.14,2489.71 2821.85,2489.71 2836.5,2504.35
  Bottom Layer w20: v1(2567.67,2467.38) 2772.99,2467.38 2903.29,2337.09 v1(2903.29,2287.83)
NetQ5_1: Q5.1 R34.1 | length 324.2
  Top Layer w20: Q5.1@1041.14,2495.08 1046.89,2489.33 1083.29,2489.33 1101.19,2471.43 1131.32,2471.43 1234.78,2367.97 1264.35,2367.97 1297.14,2335.18 R34.1@1297.14,2333.21
NetR2_2: R2.2 U2.5 | length 80.8
  Top Layer w20: U2.5@1629.92,463.83 1629.92,461.87 1628.1,460.05 1628.1,420.05 1639.82,408.33 1658.98,408.33 1659.14,408.17 R2.2@1659.14,407.84
NetR3_1: R3.1 R4.2 | length 48.2
  Top Layer w20: R3.1@1574.8,610.09 R4.2@1623.03,610.09
NetR15_2: R15.2 R16.1 | length 49.6
  Top Layer w20: R16.1@2924.86,1671.26 2925.35,1671.76 2925.35,1719.99 R15.2@2925.84,1720.48
NetR20_pta_I1_1: R20_pta_I1.1 U1.24 | length 1880
  Top Layer w10: 659.01,1359.28 663.37,1363.64 683.76,1363.64 U1.24@720.03,1363.64
  Top Layer w20: R20_pta_I1.1@374.02,2602.36 374.02,2398.23 354.49,2378.71 354.49,2363.32 298.7,2307.53 298.7,1264.25 356.47,1206.47 507.46,1206.47 659.64,1358.65
NetR20_pta_I2_1: R20_pta_I2.1 U1.23 | length 1591.4
  Top Layer w10: 638.92,1379.65 642.59,1383.33 719.72,1383.33 U1.23@720.03,1383.33
  Top Layer w20: R20_pta_I2.1@399.56,2368.64 396.77,2365.85 396.77,2363.88 328.2,2295.31 328.2,1276.47 368.69,1235.97 462.31,1235.97 533.36,1307.03 566.29,1307.03 638.92,1379.65
NetR20_pta_I3_1: R20_pta_I3.1 U1.28 | length 2297.1
  Top Layer w10: U1.28@822.4,1280.96 822.74,1280.62 822.74,1211.72 842.08,1192.38
  Top Layer w20: 842.08,1192.38 895.07,1139.4 895.07,1136.27 910.31,1121.03 v1(910.31,1110.46) ; v1(1364.82,1106.69) 1909.41,1106.69 2032.65,983.45 2729.85,983.45 2834.8,1088.4 2836.77,1088.4 R20_pta_I3.1@2839.57,1091.2
  Bottom Layer w20: v1(910.31,1110.46) 1049.65,1110.46 1130.34,1029.77 1287.89,1029.77 v1(1364.82,1106.69)
NetR23_2: R23.2 U4.10 | length 106.2
  Top Layer w20: U4.10@478.03,377.55 478.03,309.08 482.93,304.17 482.93,280.23 R23.2@487.77,275.39
NetR24_1: R24.1 U4.7 | length 100.5
  Top Layer w20: U4.7@478.03,739.75 478.62,740.35 478.62,839.18 R24.1@479.21,839.77
NetR24_2: R24.2 U1.46 | length 1155.4
  Top Layer w10: U1.46@1176.73,1280.96 1176.72,1230.22 1184.33,1222.61 1184.33,1198.82 1199.97,1183.17 1228.72,1183.17
  Top Layer w20: R24.2@440.51,839.77 442.32,841.58 442.32,853.77 521.61,933.06 1018.31,933.06 1057.04,971.79 1060.14,971.79 1118.12,1029.77 1176.1,1029.77 1256.03,1109.69 1256.03,1155.87 1228.72,1183.17
NetR25_2: R25.2 U4.11 | length 104.1
  Top Layer w20: R25.2@528.03,273.43 U4.11@528.03,377.55
NetR26_1: R26.1 U4.6 | length 101.2
  Top Layer w20: U4.6@528.03,739.75 529.5,741.23 529.5,838.3 R26.1@530.98,839.77
NetR26_2: R26.2 U1.47 | length 1075.8
  Top Layer w10: U1.47@1196.41,1280.96 1196.76,1280.62 1196.76,1237.76 1203.83,1230.69 1203.83,1213.97 1210.12,1207.67
  Top Layer w20: R26.2@569.68,839.77 645.86,839.77 675.28,869.19 1020.57,869.19 1151.64,1000.27 1188.32,1000.27 1285.53,1097.47 1285.53,1181.12 1253.97,1212.67 1216.5,1212.67 1211.5,1207.67 1210.12,1207.67
NetR29_1: R29.1 R30.2 U1.27 | length 1951
  Top Layer w10: U1.27@802.71,1280.96 802.71,1183.4 810.97,1175.14
  Top Layer w20: 810.97,1175.14 823.5,1162.61 v1(823.5,1106.69) ; v1(1821.23,2113.15) 1824.83,2109.55 1869.05,2109.55 ; R29.1@1869.05,2141.46 1869.05,2109.55 ; R30.2@1871.01,2087.9 1869.05,2089.86 1869.05,2109.55
  Bottom Layer w20: v1(823.5,1106.69) 823.5,1117.96 1041.14,1335.6 1482.54,1335.6 1557.96,1411.02 1558,1416.25 1560.6,1420.81 1595.86,1482.47 1597.19,1484.79 1609.49,1497.09 1609.49,1584.46 1611.42,1587.04 1614.46,1590.5 1821.23,1826.1 v1(1821.23,2113.15)
NetR31_2: R31.2 U5.1 | length 640.9
  Top Layer w20: v1(1099.89,2391.81) 1135.64,2356.05 1135.64,2346.19 1143.86,2337.97 1143.86,2336 R31.2@1146.65,2333.21 ; U5.1@1314.42,2803.15 1328.2,2803.15 1369.54,2761.81 v1(1375.86,2761.81)
  Bottom Layer w20: v1(1099.89,2391.81) 1099.89,2408.84 1375.86,2684.82 v1(1375.86,2761.81)
NetSW2_1: SW2.1 U1.72 | length 2161.2
  Top Layer w10: U1.72@1318.46,1757.34 1393.02,1757.34 1428.79,1793.1 1428.79,1811.53 1479.25,1862 1627.06,1862 v1(1631.77,1866.71)
  Bottom Layer w20: v1(1631.77,1866.71) 1616.71,1866.71 1612.25,2035.44 1612.25,2035.71 1612.25,2061.86 1638.4,2088.01 1638.4,2127.34 1683.98,2172.92 1683.98,3138.42 1827.51,3281.95 1924.99,3281.95 SW2.1@2048.55,3405.51
NetSW2_3: SW2.3 U1.68 | length 2805.1
  Top Layer w10: U1.68@1318.46,1678.6 1444.68,1678.6
  Top Layer w20: 1444.68,1678.6 1449.65,1678.6 1459.13,1669.12 1553.54,1669.12 v1(1631.77,1747.35)
  Bottom Layer w20: v1(1631.77,1747.35) 1703.23,1818.81 1703.23,1844.85 1716.93,1858.56 1716.93,2119.91 1742.98,2145.96 1742.98,3052.51 1913.42,3222.95 1994.34,3222.95 2373.75,3602.37 SW2.3@2619.42,3602.37
NetSW2_5: SW2.5 U1.67 | length 2500.7
  Top Layer w10: U1.67@1318.46,1658.92 1429.71,1658.92 1444.01,1644.62 1591.3,1644.62 1742.87,1796.18 1742.87,1815.16 v1(1752.25,1824.54)
  Bottom Layer w20: v1(1752.25,1824.54) 1752.25,2113.51 1829.25,2190.51 1889.36,2190.51 2244.03,2545.18 2244.03,3030.12 SW2.5@2619.42,3405.51
NetSW3_1: SW3.1 U1.76 | length 3186.6
  Top Layer w10: U1.76@1255.47,1879.39 1255.47,1908.99 1256.3,1909.82 1336.84,1909.82 1351.7,1924.68
  Top Layer w20: 1351.7,1924.68 1478.08,1924.68 1550.14,1996.74 v1(1667.9,1996.74)
  Bottom Layer w20: v1(1667.9,1996.74) 1667.9,2115.12 1713.48,2160.7 1713.48,3064.73 1901.2,3252.45 1982.12,3252.45 2390.9,3661.24 2767.89,3661.24 SW3.1@2994.09,3435.04
NetSW4_1: SW4.1 U1.73 | length 1949
  Top Layer w10: U1.73@1318.46,1777.03 1385.13,1777.03 1409.29,1801.18 1409.29,1854.3 v1(1411.14,1856.15)
  Bottom Layer w20: SW4.1@1014.69,3405.51 1014.69,3306.39 1506.3,2814.78 1506.3,1951.31 v1(1411.14,1856.15)
NetSW4_3: SW4.3 U1.54 | length 2454
  Top Layer w10: U1.54@1318.46,1403.01 1318.62,1403.17 1377.17,1403.17 v1(1432,1458)
  Bottom Layer w20: v1(1432,1458) 1484.22,1458 1550.49,1524.27 1550.49,1702.46 1553.25,1705.22 1553.25,2116.07 1567.69,2116.07 1579.4,2127.78 1579.4,2975.68 1494.06,3061.02 1494.06,3510.87 SW4.3@1585.55,3602.36
NetSW4_5: SW4.5 U1.53 | length 2279.1
  Top Layer w10: U1.53@1318.46,1383.33 1354.38,1383.33 1354.73,1383.67 1461.28,1383.67 v1(1462.23,1384.62)
  Bottom Layer w20: v1(1462.23,1384.62) 1462.23,1391.56 1579.99,1509.31 1579.99,1690.24 1582.75,1693 1582.75,2074.08 1608.9,2100.23 1608.9,3232.91 1661.38,3285.39 1661.38,3329.69 SW4.5@1585.55,3405.51
NetSW5_1: SW5.1 U1.74 | length 3088.6
  Top Layer w10: U1.74@1318.46,1796.71 1377.24,1796.71 1385.64,1805.11 1385.64,1813.4 1364.7,1834.34 1364.22,1834.34 1364.22,1885.49 1378.92,1900.18 1579.4,1900.18 1585.97,1906.75
  Top Layer w20: 1585.97,1906.75 1626.47,1947.25 1778.18,1947.25 1938.2,1787.22 1938.2,1622.47 2499.67,1061 v1(2631.89,1061)
  Bottom Layer w20: v1(2631.89,1061) 2948.88,744.01 2948.88,151.52 SW5.1@3041.34,59.05
NetSW6_1: SW6.1 U1.77 | length 3576.1
  Top Layer w10: U1.77@1235.78,1880.11 1235.78,1933.63 1242.2,1940.04 1315.48,1940.04 1329.62,1954.18
  Top Layer w20: 1329.62,1954.18 1465.86,1954.18 1579.69,2068.01 1579.69,2076.18 1591.41,2087.9 1679.25,2087.9 1967.7,1799.44 1967.7,1698.1 2221.24,1444.56 2231.02,1444.56 v1(2300.06,1375.52)
  Bottom Layer w20: v1(2300.06,1375.52) 2310.63,1375.52 2333.01,1353.15 2351.17,1353.15 2551.11,1153.21 2647.64,1153.21 2978.38,822.47 2978.38,229.85 2999,209.22 2999,186 3037.36,147.64 3340.55,147.64 SW6.1@3429.13,59.05
NetSW7_1: SW7.1 U1.78 | length 2040
  Top Layer w10: U1.78@1216.1,1879.39 1216.1,1941.52 1234.12,1959.54 1300.33,1959.54 1319.48,1978.68 1432.42,1978.68 1521.75,2068.01
  Top Layer w20: v1(1457.28,2229.05) 1521.75,2164.57 1521.75,2068.01
  Bottom Layer w20: SW7.1@864,3415.36 1457.28,2822.08 v1(1457.28,2229.05)
NetU4_3: U4.3 U4.4 U4.5 | length 100
  Top Layer w20: U4.5@578.03,739.75 U4.4@628.03,739.75 U4.3@678.03,739.75
PGND: *2.2 C13.1 C14.1 C15.1 C16.1 C17.2 C18.2 C19.2 C20.1 C21.1 C22.1 C23.1 C24.1 C25.1 C26.1 C45.1 C47.1 C48.1 IC1.22 IC1.- IC2.1 ISO1.4 P1.1 Q5.2 R2.1 R4.1 R11.1 R12.2 R17.1 R19.1 R27.2 R32.1 R33.1 U2.2 U4.16 | length 16687.1
  Top Layer w10: v3(2842.52,2055.12) IC1.-@2845.47,2052.17
  Top Layer w12: 626.39,2852.36 649.17,2852.36 663.07,2866.27 663.07,2897.95 IC2.1@663.07,2917.03
  Top Layer w15: 1677.17,529.78 1677.17,523.45 1699.38,501.23 U2.2@1703.45,501.23 ; R2.1@1699.14,407.84 1766.03,407.84 1770.46,403.41 ; IC1.-@2665.35,2019.69 IC1.22@2665.35,2122.05 ; IC1.-@2845.47,2052.17 2882.53,2089.23 2882.53,2143.45
  Top Layer w20: v1(408.34,150.9) 415.82,158.37 415.82,187.01 428.03,199.22 428.03,211.7 ; C45.1@428.03,237.99 428.03,211.7 ; R27.2@460.49,2960.18 511.97,2960.18 533.17,2938.98 533.17,2898.06 578.86,2852.36 626.39,2852.36 ; U4.16@778.03,377.55 778.03,464.6 735.94,506.69 408.27,506.69 347.12,445.55 347.12,256.69 392.12,211.7 428.03,211.7 ; v1(839.11,717.24) 1001.81,717.24 1317.92,1033.34 1644.3,1033.34 1655.72,1021.92 1655.72,990.12 1667.44,978.41 C15.1@1719.88,978.41 ; R32.1@1006.45,2333.21 1013.69,2325.97 1013.69,2303.45 1036.96,2280.18 1168.31,2280.18 1178.31,2290.18 1178.31,2309.3 1200.25,2331.24 R33.1@1200.25,2333.21 1197.45,2336 1197.45,2337.97 1158.82,2376.6 1158.82,2402.21 1120.19,2440.84 1034.34,2440.84 1003.92,2471.25 1003.92,2518.9 1018.38,2533.36 1119.16,2533.36 1128.28,2542.48 1171.57,2542.48 *2.2@1173.38,2544.29 ; Q5.2@1041.14,2569.88 1046.89,2564.13 1067.25,2564.13 1099.89,2531.5 v1@1105.49,2531.5 ; C16.1@1660.83,894.75 1703.64,894.75 1710.53,901.64 C14.1@1753.35,901.64 ; R4.1@1666.34,610.09 1666.34,569.16 1677.17,558.33 1677.17,529.78 ; U2.2@1703.45,501.23 U2.2@1724.41,501.23 1727.2,498.43 1755.77,498.43 1770.46,483.74 1770.46,420.52 ; 1719.88,901.64 C15.1@1719.88,978.41 ; 1770.46,403.41 1770.46,420.52 ; 2227.39,471.94 2227.5,471.82 ; 2267.08,471.82 2309.57,429.33 2309.57,367.47 2280.85,338.75 2091.84,338.75 2061.33,369.26 1872.32,369.26 1823.03,418.55 R19.1@1821.06,418.55 1772.43,418.55 1770.46,420.52 ; v1(2277.84,649.29) 2270.37,656.77 2241.88,656.77 2240.74,657.91 2232.3,657.91 1920.67,969.55 C13.1@1920.67,978.41 1868.22,978.41 1856.51,990.12 1856.51,1021.92 1845.08,1033.34 1765.96,1033.34 1719.88,987.27 C15.1@1719.88,978.41 ; IC1.-@2665.35,2019.69 IC1.-@2677.17,2007.87 v2(2700.79,2007.87) v2(2748.03,2007.87) v3(2795.28,2007.87) 2801.18,2007.87 IC1.-@2845.47,2052.17 ; 2882.53,2143.45 2944.7,2205.62 2944.7,2223.59 R12.2@2947.5,2226.38
  Top Layer w35: R27.2@460.49,2960.18 460.49,2844.32 481,2823.82 885.51,2823.82 903.01,2806.32 911.87,2806.32 C48.1@920.78,2797.41 ; C48.1@920.94,2797.25 C48.1@920.78,2797.41 ; C47.1@1417.32,2838.58 C47.1@1421.26,2838.58 ; P1.1@2065.94,545.21 2154.11,545.21 2227.39,471.94 ; C19.2@2083.92,2705.57 2055.08,2734.41 C19.2@2055.08,2750.99 C18.2@1661.38,2750.99 1508.86,2750.99 C47.1@1421.26,2838.58 ; C22.1@2144.11,2647.64 2130.03,2661.71 2130.03,2694.46 2118.92,2705.57 2108.21,2705.57 2095.03,2692.39 2095.03,2602.89 2108.21,2589.71 2112.95,2589.71 2144.1,2558.55 C21.1@2144.1,2549.7 2144.1,2540.84 C20.1@2144.1,2449.8 2153.18,2440.73 2153.18,2431.87 2197.68,2387.37 2484.11,2387.37 2507.59,2410.85 2591.08,2410.85 2604.72,2424.49 2696.95,2424.49 R11.1@2700.67,2428.21 ; v1(2308.44,524.87) 2301.94,524.87 2282.86,505.79 2261.48,505.79 2227.5,471.82 2267.08,471.82 2468.96,471.82 3032.09,1034.94 3405,1407.85 3405,2373.48 3664.8,2633.28 3664.8,3470.47 3644.29,3490.98 3504.49,3490.98 3483.99,3470.47 3483.99,2771.49 3463.49,2750.99 C17.2@3346.42,2750.99 C17.2@3346.42,2750.99 v1(3346.46,2620.56) ; R11.1@2704.39,2431.93 2782.93,2431.93 2786.22,2435.21 2873.63,2435.21 2931.81,2377.03 C23.1@3001.98,2377.03 3124.12,2377.03 3143.7,2396.61 C24.1@3143.7,2440.95 C25.1@3143.7,2522.4 C26.1@3143.7,2602.2 3321.34,2602.2 ; R17.1@3074.8,1645.35 v1(3119.66,1645.35) ; C48.1@920.78,2797.41 1043.83,2797.41 v1(1131.45,2709.78) 1137.96,2709.78 1148.92,2698.82 1411.89,2698.82 1432.39,2719.32 1432.39,2785.23 1427.38,2790.24 1427.38,2832.46 C47.1@1421.26,2838.58
  Bottom Layer w20: ISO1.4@651.91,198.62 604.18,150.9 v1(408.34,150.9) 408.34,286.47 v1(839.11,717.24) ; v1(1108.59,2533.36) 1108.59,2676.36 1131.45,2699.22 v1(1131.45,2709.78) ; v1(2277.84,649.29) 2277.84,638.72 2308.44,608.12 v1(2308.44,524.87)
  Bottom Layer w35: v1(3119.66,1645.35) 3232.28,1757.98 3232.28,1929.13 3199.8,1961.61 v1(3199.8,2162.21)
  other v2: 2606.3,1960.63 2653.54,1960.63 2700.79,1960.63 2748.03,1960.63 2606.3,2007.87 2653.54,2007.87 2606.3,2055.12 2653.54,2055.12 2700.79,2055.12 2748.03,2055.12
  other v3: 2795.28,1960.63 2842.52,1960.63 2842.52,2007.87 2795.28,2055.12
  other v4: 2511.81,1960.63 2559.06,1960.63 2511.81,2007.87 2559.06,2007.87 2511.81,2055.12 2559.06,2055.12
V_out: C31.2 IC1.24 | length 546.2
  Top Layer w15: C31.2@2198.61,2269.53 2216.33,2269.53 2248.65,2301.85 2410.39,2301.85 2469.24,2243 2566.3,2243 2613.08,2196.22 2613.08,2171.28 2614.17,2170.19 IC1.24@2614.17,2122.05
pads on no net: *1_pta_I1.5 *1_pta_I2.5 *1_pta_I3.5 *2.5 Display.1 Display.2 Display.3 Display.4 Display.5 Display.6 Display.7 Display.8 Display.9 Display.10 Display.11 Display.12 Display.13 Display.14 Display.15 Display.16 Display.17 Display.18 Display.19 Display.20 Display.27 Display.29 Display.30 Display.31 Display.32 J1. J1.A5 J1.A8 J1.B5 J1.B8 J2.4 SW1.1 SW1.4 SW1.5 SW1.6 SW3.2 SW3.4 SW5.2 SW5.4 SW6.2 SW6.4 SW7.2 SW7.4 U1.1 U1.2 U1.3 U1.4 U1.5 U1.7 U1.8 U1.9 U1.11 U1.22 U1.29 U1.30 U1.31 U1.32 U1.33 U1.34 U1.35 U1.36 U1.40 U1.41 U1.42 U1.43 U1.48 U1.49 U1.51 U1.52 U1.55 U1.56 U1.57 U1.58 U1.59 U1.60 U1.61 U1.62 U1.79 U1.89 U1.90 U1.91 U1.92 U1.93 U1.94 U1.95 U1.96 U1.97 U1.98 U1.99 U3.4 U5.4
copper on no net:
  other v5: 168.5,256.69 3768.5,256.69 168.5,2656.69 3768.5,2656.69

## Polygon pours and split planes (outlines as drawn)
GND on Top Layer "GND" (solid, pour order 15): -2.19,3937.01 3937.01,3937.01 3937.01,0 0,0
PGND on Top Layer "PGND" (solid, pour order 10): 0,3937.01 3937.01,3937.01 3937.01,1574.27 1732.28,1574.27 1732.28,2233.21 0,2233.21
NetC18_1 on Top Layer "NETC18_1_L01_P008" (solid, pour order 8): 2355.77,2734.41 2376.89,2713.29 2376.89,2477.42 2364.63,2477.42 2291.58,2404.37 2217.77,2404.37 2222.4,2901.58 2198.29,2901.58 2171.66,2901.58 1334.3,2901.58 1251.62,2984.25 1251.62,3061.02 1346.11,3155.51 2198.29,3155.51 2355.77,2998.03
NetC32_1 on Top Layer "PGND" (solid, pour order 7): 2365.61,3119.1 2677.67,3119.09 2677.67,2560.38 2674.86,2557.57 2432.54,2557.57 2365.61,2624.5 2365.61,3070.87
NetC28_1 on Top Layer "PGND" (solid, pour order 6): 2886.81,2685.04 2887.5,2684.34 2887.74,2615.69 2949.8,2553.63 2949.8,2494.85 2930.72,2494.85 2860.76,2564.8 2687.99,2564.8 2687.99,2702.05 2687.99,3120.47 3000.98,3117.59 3000.98,2799.21
NetQ3_1 on Top Layer "NETQ3_1_L01_P005" (solid, pour order 5): 2537.98,2458.72 2836.62,2458.72 2866.02,2488.12 2866.02,2559.54 2537.98,2559.54
GND on Top Layer "GND" (solid, pour order 16): 2137.6,-590.55
no net on Top Layer "PGND" (solid, pour order 9): -1.97,3544.29
PGND on Top Layer "PGND" (solid, pour order 1): 1732.28,2471.06 2274.21,1929.13 3116.61,1929.13 3543.31,2355.83 3543.31,2862.2 3289.37,2862.2 3110.24,2683.07 3110.24,2441.99 2222.4,2441.99 2222.4,2517.11 2222.4,2883.86 1142.72,2883.86 1020.67,3005.91 1020.67,3121.92 916.3,3121.92 820.81,3026.43 820.81,2667.32 1017.07,2471.06
NetC17_1 on Top Layer "NETC17_1_L01_P000" (solid, pour order 0): 3450.75,3149.61 3450.75,2874.02 3284.75,2874.02 3100.39,2689.66 3110.24,2679.82 3110.24,2416.14 2961.37,2416.14 2961.37,2754.68 3182.9,2976.21 3182.9,3149.61
no net on Top Layer "PGND" (solid, pour order 4): 3385.83,2913.39
no net on Top Layer "PGND" (solid, pour order 3): 3053.15,2933.07
no net on Top Layer "PGND" (solid, pour order 2): 3622.05,1090.55
GND on Bottom Layer "GND" (solid, pour order 17): -7.66,3937.01 -7.66,-15.31 3937.01,-15.31 3937.01,3936.25
PGND on Bottom Layer "PGND" (solid, pour order 14): 2102.78,1659.16 2263.33,1498.6 3287.24,1498.6 3391,1602.36 3382.99,1610.37 3382.99,2307.49 3321.34,2369.15 3305.59,2353.4 2159.41,2353.4 2102.78,2296.77
PGND on Bottom Layer "PGND" (solid, pour order 13): 6496.06,2086.61

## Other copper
Top Layer:
  text "+" at 190,3157.03 h39.37 r90
  text "-" at 190,2845 h39.37 r90
  text "-" at 2043.53,453.77 h39.37
  text "+" at 1946.28,447.74 h39.37
  text "Power Supply / Simen Sollihogda / rev2 / .Print_Date" at 2873.03,400.79 h39.37
Bottom Layer:
  text "-" at 2043.53,453.77 h39.37
  text "+" at 1946.28,447.74 h39.37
